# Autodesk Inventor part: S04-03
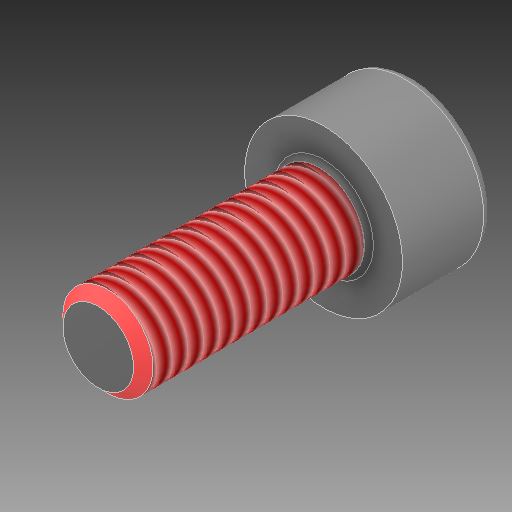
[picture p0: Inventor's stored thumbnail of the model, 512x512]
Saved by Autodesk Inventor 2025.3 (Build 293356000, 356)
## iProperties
Manager: ISO 4762 (DIN 912)
Created: 2025-05
Part Number: S04-03
Material: Všeobecné
Document SubType Name: Modeling
Designer: Patrik
Density: 1 g/cm^3
Appearance: Výchozí
Description: Imbusový šroub s válcovou hlavou
Stock Number: E 1200/4x10
User Status: 12.9
Mass: 0.262335 g
Surface Area: 3.03076 cm^2
Volume: 0.262335 cm^3
Sending System: KiM GmbH
Major Version: 4.0
Minor Version: 0.0
Format Version: 0.0
Product Id: KiM GmbH
cc_prop_force_one_body: 1
Hersteller: Meusburger
Material: 12.9 ISO 4762 (DIN 912)
Bestellnummer: E 1200/4x10
Teilenummer: E 1200/4x10
Beschreibung: Zylinderkopfschraube mit Innensechskant _ Cylinder head screw with hexagon socket
Author: Patrik
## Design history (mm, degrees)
feature "E 1200_4x10_1_1:1"
feature "Závit1" dims "d0" = 9.37, "d1" = 0
node "Těleso1"
